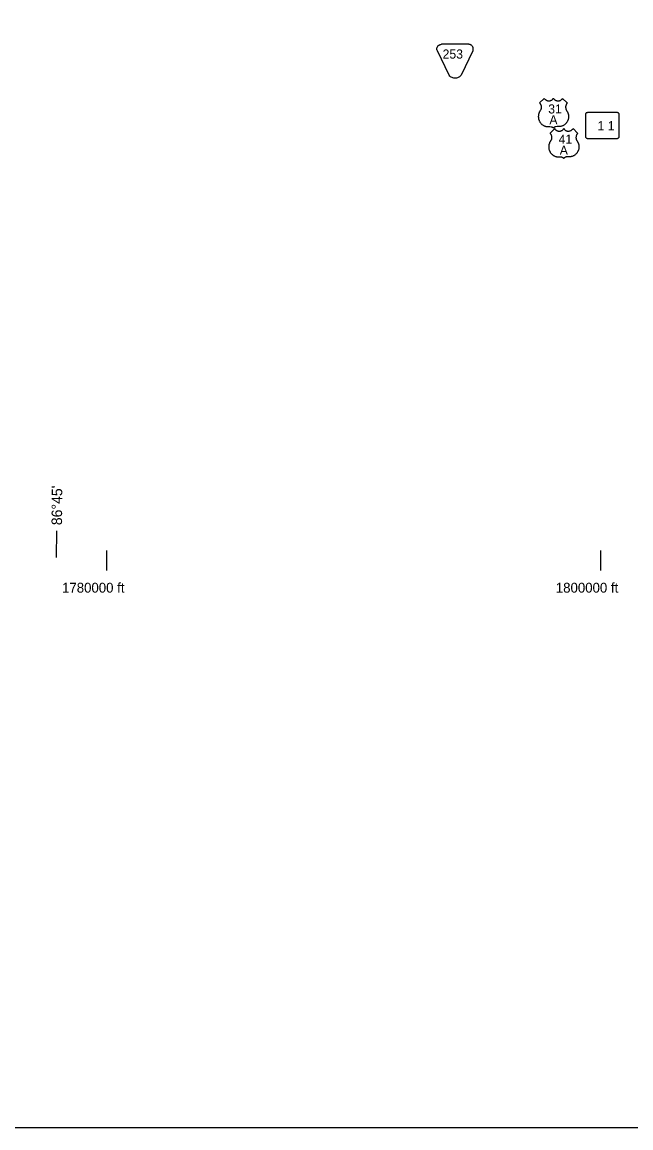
# Model space of a CAD drawing. Extents: x 1612280 to 1883141, y 560852 to 780851.
# Drawn here: x 1745083 to 1769718, y 560852 to 605620 of the extents above; entities that cross this region are included whole.
import ezdxf

# ---------------------------------------------------------------- set-up
doc = ezdxf.new("R2010")
doc.units = 0
for name, color, linetype in [('DESIGN - ROW - Easement Linework and Patterning', 7, 'Continuous'), ('DESIGN - ROW - Slope Lines', 7, 'Continuous'), ('DESIGN - SCRATCH - User 1', 7, 'Continuous'), ('SURVEY - DRAINAGE - Bridge Deck with Text', 7, 'Continuous'), ('SURVEY - DRAINAGE - Bridge Hydraulic Data - Points - Locators', 7, 'Continuous'), ('SURVEY - NON-TRANSPORTATION - Features - Points - Locators', 7, 'Continuous')]:
    doc.layers.add(name, color=color, linetype=linetype)

msp = doc.modelspace()

# ---------------------------------------------------------------- linework, layer by layer
at = {"layer": 'DESIGN - ROW - Easement Linework and Patterning'}
for points in [[(1762361, 603475), (1761886, 604456), (1761876, 604482), (1761871, 604501), (1761869, 604518), (1761868, 604534), (1761869, 604552), (1761871, 604568), (1761876, 604592), (1761883, 604609), (1761891, 604625), (1761901, 604641), (1761911, 604655), (1761927, 604671), (1761941, 604683), (1761954, 604692), (1761967, 604700), (1761983, 604707), (1761999, 604713), (1762012, 604716), (1762033, 604720), (1762053, 604721)], [(1762361, 603475), (1761886, 604456), (1761876, 604482), (1761871, 604501), (1761869, 604518), (1761868, 604534), (1761869, 604552), (1761871, 604568), (1761876, 604592), (1761883, 604609), (1761891, 604625), (1761901, 604641), (1761911, 604655), (1761927, 604671), (1761941, 604683), (1761954, 604692), (1761967, 604700), (1761983, 604707), (1761999, 604713), (1762012, 604716), (1762033, 604720), (1762053, 604721)], [(1763323, 604456), (1763330, 604473), (1763338, 604496), (1763340, 604513), (1763342, 604533), (1763341, 604549), (1763339, 604567), (1763334, 604589), (1763328, 604607), (1763321, 604622), (1763312, 604637), (1763300, 604653), (1763288, 604667), (1763269, 604683), (1763254, 604693), (1763240, 604701), (1763226, 604707), (1763210, 604713), (1763190, 604718), (1763176, 604720), (1763157, 604721), (1762053, 604721)], [(1763323, 604456), (1763330, 604473), (1763338, 604496), (1763340, 604513), (1763342, 604533), (1763341, 604549), (1763339, 604567), (1763334, 604589), (1763328, 604607), (1763321, 604622), (1763312, 604637), (1763300, 604653), (1763288, 604667), (1763269, 604683), (1763254, 604693), (1763240, 604701), (1763226, 604707), (1763210, 604713), (1763190, 604718), (1763176, 604720), (1763157, 604721), (1762053, 604721)], [(1763323, 604456), (1762850, 603478), (1762835, 603458), (1762821, 603441), (1762807, 603428), (1762779, 603405), (1762757, 603391), (1762733, 603378), (1762700, 603364), (1762663, 603354), (1762631, 603350), (1762596, 603349), (1762559, 603352), (1762518, 603361), (1762482, 603375), (1762447, 603394), (1762425, 603409), (1762395, 603434), (1762361, 603475)], [(1763323, 604456), (1762850, 603478), (1762835, 603458), (1762821, 603441), (1762807, 603428), (1762779, 603405), (1762757, 603391), (1762733, 603378), (1762700, 603364), (1762663, 603354), (1762631, 603350), (1762596, 603349), (1762559, 603352), (1762518, 603361), (1762482, 603375), (1762447, 603394), (1762425, 603409), (1762395, 603434), (1762361, 603475)]]:
    msp.add_lwpolyline(points, dxfattribs=at)
at = {"layer": 'DESIGN - ROW - Slope Lines'}
msp.add_line((1767876, 601855), (1767876, 601023), dxfattribs=at)
msp.add_line((1767876, 601855), (1767876, 601023), dxfattribs=at)
for points in [[(1769249, 601844), (1769249, 601852), (1769248, 601860), (1769247, 601875), (1769246, 601885), (1769244, 601896), (1769242, 601902), (1769239, 601908), (1769235, 601916), (1769229, 601923), (1769225, 601929), (1769219, 601934), (1769214, 601938), (1769208, 601943), (1769203, 601946), (1769194, 601950), (1769188, 601952), (1769181, 601953), (1769172, 601955), (1769164, 601955), (1769155, 601956), (1769143, 601956), (1769133, 601955), (1767976, 601956), (1767966, 601956), (1767956, 601955), (1767947, 601954), (1767938, 601953), (1767934, 601951), (1767926, 601948), (1767920, 601945), (1767915, 601942), (1767906, 601935), (1767900, 601929), (1767895, 601923), (1767891, 601918), (1767885, 601908), (1767882, 601901), (1767880, 601896), (1767879, 601892), (1767878, 601889), (1767878, 601881), (1767876, 601872), (1767876, 601864), (1767876, 601857), (1767876, 601839)], [(1769249, 601844), (1769249, 601852), (1769248, 601860), (1769247, 601875), (1769246, 601885), (1769244, 601896), (1769242, 601902), (1769239, 601908), (1769235, 601916), (1769229, 601923), (1769225, 601929), (1769219, 601934), (1769214, 601938), (1769208, 601943), (1769203, 601946), (1769194, 601950), (1769188, 601952), (1769181, 601953), (1769172, 601955), (1769164, 601955), (1769155, 601956), (1769143, 601956), (1769133, 601955), (1767976, 601956), (1767966, 601956), (1767956, 601955), (1767947, 601954), (1767938, 601953), (1767934, 601951), (1767926, 601948), (1767920, 601945), (1767915, 601942), (1767906, 601935), (1767900, 601929), (1767895, 601923), (1767891, 601918), (1767885, 601908), (1767882, 601901), (1767880, 601896), (1767879, 601892), (1767878, 601889), (1767878, 601881), (1767876, 601872), (1767876, 601864), (1767876, 601857), (1767876, 601839)], [(1769139, 600914), (1769160, 600914), (1769177, 600914), (1769187, 600917), (1769199, 600921), (1769210, 600928), (1769219, 600935), (1769227, 600943), (1769233, 600951), (1769239, 600960), (1769243, 600968), (1769246, 600975), (1769247, 600983), (1769248, 600991), (1769248, 601001), (1769249, 601024), (1769249, 601844)], [(1769139, 600914), (1769160, 600914), (1769177, 600914), (1769187, 600917), (1769199, 600921), (1769210, 600928), (1769219, 600935), (1769227, 600943), (1769233, 600951), (1769239, 600960), (1769243, 600968), (1769246, 600975), (1769247, 600983), (1769248, 600991), (1769248, 601001), (1769249, 601024), (1769249, 601844)], [(1767876, 601023), (1767876, 601014), (1767877, 601004), (1767877, 600994), (1767878, 600985), (1767880, 600976), (1767883, 600968), (1767886, 600961), (1767891, 600954), (1767896, 600946), (1767902, 600940), (1767909, 600933), (1767916, 600928), (1767924, 600923), (1767932, 600919), (1767941, 600916), (1767949, 600915), (1767963, 600914), (1767982, 600914), (1769139, 600914)], [(1767876, 601023), (1767876, 601014), (1767877, 601004), (1767877, 600994), (1767878, 600985), (1767880, 600976), (1767883, 600968), (1767886, 600961), (1767891, 600954), (1767896, 600946), (1767902, 600940), (1767909, 600933), (1767916, 600928), (1767924, 600923), (1767932, 600919), (1767941, 600916), (1767949, 600915), (1767963, 600914), (1767982, 600914), (1769139, 600914)]]:
    msp.add_lwpolyline(points, dxfattribs=at)
at = {"layer": 'DESIGN - SCRATCH - User 1'}
msp.add_lwpolyline([(1612280, 780851), (1883141, 780851), (1883141, 560852), (1612280, 560852)], close=True, dxfattribs=at)
msp.add_lwpolyline([(1612280, 780851), (1883141, 780851), (1883141, 560852), (1612280, 560852)], close=True, dxfattribs=at)
at = {"layer": 'SURVEY - DRAINAGE - Bridge Deck with Text'}
for points in [[(1766026, 602346), (1766035, 602336), (1766043, 602325), (1766051, 602314), (1766057, 602304), (1766064, 602291), (1766071, 602277), (1766076, 602263), (1766081, 602248), (1766085, 602233), (1766088, 602217), (1766091, 602200), (1766092, 602178), (1766092, 602162), (1766090, 602146), (1766088, 602132), (1766084, 602113), (1766080, 602100), (1766076, 602086), (1766071, 602074), (1766066, 602064), (1766058, 602050), (1766051, 602038), (1766040, 602020), (1766028, 601999), (1766024, 601993), (1766018, 601982), (1766011, 601969), (1766007, 601960), (1766002, 601948), (1765998, 601938), (1765994, 601927), (1765991, 601915), (1765987, 601903), (1765983, 601889), (1765981, 601878), (1765979, 601866), (1765977, 601854), (1765975, 601841), (1765974, 601830), (1765973, 601818), (1765972, 601807), (1765972, 601796), (1765972, 601784), (1765973, 601772), (1765974, 601758), (1765976, 601743), (1765978, 601727), (1765981, 601713), (1765984, 601696), (1765989, 601677), (1765994, 601663), (1766001, 601645), (1766007, 601631), (1766012, 601620), (1766019, 601605), (1766029, 601588), (1766038, 601573), (1766050, 601555), (1766062, 601539), (1766076, 601523), (1766091, 601507), (1766103, 601496), (1766120, 601481), (1766140, 601465), (1766164, 601449), (1766184, 601437), (1766204, 601427), (1766222, 601419), (1766242, 601411), (1766262, 601405), (1766281, 601400), (1766291, 601397), (1766304, 601396), (1766334, 601393), (1766439, 601390), (1766487, 601387), (1766492, 601387), (1766496, 601386), (1766502, 601384), (1766507, 601383), (1766511, 601381), (1766516, 601380), (1766521, 601377), (1766526, 601375), (1766531, 601373), (1766535, 601371), (1766539, 601369), (1766547, 601363), (1766556, 601356), (1766565, 601349), (1766572, 601342), (1766579, 601334), (1766584, 601326)], [(1766026, 602346), (1766035, 602336), (1766043, 602325), (1766051, 602314), (1766057, 602304), (1766064, 602291), (1766071, 602277), (1766076, 602263), (1766081, 602248), (1766085, 602233), (1766088, 602217), (1766091, 602200), (1766092, 602178), (1766092, 602162), (1766090, 602146), (1766088, 602132), (1766084, 602113), (1766080, 602100), (1766076, 602086), (1766071, 602074), (1766066, 602064), (1766058, 602050), (1766051, 602038), (1766040, 602020), (1766028, 601999), (1766024, 601993), (1766018, 601982), (1766011, 601969), (1766007, 601960), (1766002, 601948), (1765998, 601938), (1765994, 601927), (1765991, 601915), (1765987, 601903), (1765983, 601889), (1765981, 601878), (1765979, 601866), (1765977, 601854), (1765975, 601841), (1765974, 601830), (1765973, 601818), (1765972, 601807), (1765972, 601796), (1765972, 601784), (1765973, 601772), (1765974, 601758), (1765976, 601743), (1765978, 601727), (1765981, 601713), (1765984, 601696), (1765989, 601677), (1765994, 601663), (1766001, 601645), (1766007, 601631), (1766012, 601620), (1766019, 601605), (1766029, 601588), (1766038, 601573), (1766050, 601555), (1766062, 601539), (1766076, 601523), (1766091, 601507), (1766103, 601496), (1766120, 601481), (1766140, 601465), (1766164, 601449), (1766184, 601437), (1766204, 601427), (1766222, 601419), (1766242, 601411), (1766262, 601405), (1766281, 601400), (1766291, 601397), (1766304, 601396), (1766334, 601393), (1766439, 601390), (1766487, 601387), (1766492, 601387), (1766496, 601386), (1766502, 601384), (1766507, 601383), (1766511, 601381), (1766516, 601380), (1766521, 601377), (1766526, 601375), (1766531, 601373), (1766535, 601371), (1766539, 601369), (1766547, 601363), (1766556, 601356), (1766565, 601349), (1766572, 601342), (1766579, 601334), (1766584, 601326)], [(1766026, 602346), (1766214, 602533), (1766223, 602519), (1766236, 602504), (1766248, 602492), (1766259, 602482), (1766271, 602473), (1766284, 602464), (1766297, 602457), (1766311, 602451), (1766324, 602445), (1766341, 602440), (1766356, 602436), (1766373, 602434), (1766390, 602432), (1766398, 602432), (1766406, 602432), (1766414, 602433), (1766424, 602434), (1766435, 602435), (1766448, 602438), (1766461, 602441), (1766479, 602447), (1766496, 602455), (1766513, 602464), (1766527, 602473), (1766540, 602483), (1766554, 602495), (1766566, 602508), (1766577, 602522), (1766585, 602533), (1766592, 602523), (1766600, 602512), (1766608, 602503), (1766618, 602493), (1766629, 602483), (1766642, 602473), (1766655, 602465), (1766669, 602457), (1766684, 602450), (1766703, 602443), (1766724, 602437), (1766745, 602434), (1766763, 602432), (1766783, 602433), (1766803, 602435), (1766824, 602439), (1766846, 602446), (1766864, 602453), (1766878, 602460), (1766895, 602471), (1766909, 602481), (1766925, 602495), (1766936, 602507), (1766946, 602519), (1766956, 602533), (1767143, 602346)], [(1766026, 602346), (1766214, 602533), (1766223, 602519), (1766236, 602504), (1766248, 602492), (1766259, 602482), (1766271, 602473), (1766284, 602464), (1766297, 602457), (1766311, 602451), (1766324, 602445), (1766341, 602440), (1766356, 602436), (1766373, 602434), (1766390, 602432), (1766398, 602432), (1766406, 602432), (1766414, 602433), (1766424, 602434), (1766435, 602435), (1766448, 602438), (1766461, 602441), (1766479, 602447), (1766496, 602455), (1766513, 602464), (1766527, 602473), (1766540, 602483), (1766554, 602495), (1766566, 602508), (1766577, 602522), (1766585, 602533), (1766592, 602523), (1766600, 602512), (1766608, 602503), (1766618, 602493), (1766629, 602483), (1766642, 602473), (1766655, 602465), (1766669, 602457), (1766684, 602450), (1766703, 602443), (1766724, 602437), (1766745, 602434), (1766763, 602432), (1766783, 602433), (1766803, 602435), (1766824, 602439), (1766846, 602446), (1766864, 602453), (1766878, 602460), (1766895, 602471), (1766909, 602481), (1766925, 602495), (1766936, 602507), (1766946, 602519), (1766956, 602533), (1767143, 602346)], [(1767143, 602346), (1767134, 602336), (1767125, 602325), (1767118, 602314), (1767111, 602304), (1767105, 602291), (1767098, 602277), (1767093, 602263), (1767087, 602248), (1767084, 602233), (1767080, 602217), (1767078, 602200), (1767077, 602178), (1767077, 602162), (1767079, 602146), (1767081, 602132), (1767085, 602113), (1767089, 602100), (1767093, 602086), (1767098, 602074), (1767103, 602064), (1767111, 602050), (1767118, 602038), (1767128, 602020), (1767141, 601999), (1767145, 601993), (1767151, 601982), (1767157, 601969), (1767162, 601960), (1767166, 601948), (1767171, 601938), (1767174, 601927), (1767178, 601915), (1767182, 601903), (1767185, 601889), (1767188, 601878), (1767190, 601866), (1767192, 601854), (1767194, 601841), (1767195, 601830), (1767196, 601818), (1767196, 601807), (1767197, 601796), (1767197, 601784), (1767196, 601772), (1767195, 601758), (1767193, 601743), (1767191, 601727), (1767188, 601713), (1767185, 601696), (1767179, 601677), (1767175, 601663), (1767168, 601645), (1767162, 601631), (1767157, 601620), (1767150, 601605), (1767140, 601588), (1767131, 601573), (1767119, 601555), (1767107, 601539), (1767093, 601523), (1767078, 601507), (1767066, 601496), (1767049, 601481), (1767029, 601465), (1767005, 601449), (1766985, 601437), (1766965, 601427), (1766947, 601419), (1766926, 601411), (1766907, 601405), (1766888, 601400), (1766878, 601397), (1766865, 601396), (1766835, 601393), (1766730, 601390), (1766682, 601387), (1766677, 601387), (1766673, 601386), (1766667, 601384), (1766662, 601383), (1766658, 601381), (1766653, 601380), (1766648, 601377), (1766643, 601375), (1766638, 601373), (1766634, 601371), (1766630, 601369), (1766622, 601363), (1766613, 601356), (1766604, 601349), (1766596, 601342), (1766590, 601334), (1766584, 601326)], [(1767143, 602346), (1767134, 602336), (1767125, 602325), (1767118, 602314), (1767111, 602304), (1767105, 602291), (1767098, 602277), (1767093, 602263), (1767087, 602248), (1767084, 602233), (1767080, 602217), (1767078, 602200), (1767077, 602178), (1767077, 602162), (1767079, 602146), (1767081, 602132), (1767085, 602113), (1767089, 602100), (1767093, 602086), (1767098, 602074), (1767103, 602064), (1767111, 602050), (1767118, 602038), (1767128, 602020), (1767141, 601999), (1767145, 601993), (1767151, 601982), (1767157, 601969), (1767162, 601960), (1767166, 601948), (1767171, 601938), (1767174, 601927), (1767178, 601915), (1767182, 601903), (1767185, 601889), (1767188, 601878), (1767190, 601866), (1767192, 601854), (1767194, 601841), (1767195, 601830), (1767196, 601818), (1767196, 601807), (1767197, 601796), (1767197, 601784), (1767196, 601772), (1767195, 601758), (1767193, 601743), (1767191, 601727), (1767188, 601713), (1767185, 601696), (1767179, 601677), (1767175, 601663), (1767168, 601645), (1767162, 601631), (1767157, 601620), (1767150, 601605), (1767140, 601588), (1767131, 601573), (1767119, 601555), (1767107, 601539), (1767093, 601523), (1767078, 601507), (1767066, 601496), (1767049, 601481), (1767029, 601465), (1767005, 601449), (1766985, 601437), (1766965, 601427), (1766947, 601419), (1766926, 601411), (1766907, 601405), (1766888, 601400), (1766878, 601397), (1766865, 601396), (1766835, 601393), (1766730, 601390), (1766682, 601387), (1766677, 601387), (1766673, 601386), (1766667, 601384), (1766662, 601383), (1766658, 601381), (1766653, 601380), (1766648, 601377), (1766643, 601375), (1766638, 601373), (1766634, 601371), (1766630, 601369), (1766622, 601363), (1766613, 601356), (1766604, 601349), (1766596, 601342), (1766590, 601334), (1766584, 601326)], [(1766446, 601121), (1766634, 601307), (1766643, 601293), (1766656, 601278), (1766668, 601266), (1766679, 601256), (1766691, 601247), (1766704, 601239), (1766717, 601232), (1766731, 601225), (1766744, 601220), (1766761, 601214), (1766776, 601211), (1766793, 601208), (1766810, 601207), (1766818, 601206), (1766826, 601207), (1766834, 601207), (1766844, 601208), (1766855, 601209), (1766868, 601212), (1766881, 601215), (1766899, 601221), (1766916, 601229), (1766933, 601238), (1766947, 601247), (1766960, 601257), (1766974, 601269), (1766986, 601282), (1766997, 601296), (1767005, 601307), (1767012, 601297), (1767020, 601286), (1767028, 601277), (1767038, 601267), (1767049, 601257), (1767062, 601248), (1767075, 601239), (1767089, 601231), (1767104, 601224), (1767123, 601217), (1767144, 601211), (1767165, 601208), (1767183, 601207), (1767203, 601207), (1767223, 601209), (1767244, 601213), (1767266, 601220), (1767284, 601227), (1767298, 601234), (1767315, 601245), (1767329, 601256), (1767345, 601270), (1767356, 601281), (1767366, 601293), (1767376, 601307), (1767563, 601121)], [(1766446, 601121), (1766634, 601307), (1766643, 601293), (1766656, 601278), (1766668, 601266), (1766679, 601256), (1766691, 601247), (1766704, 601239), (1766717, 601232), (1766731, 601225), (1766744, 601220), (1766761, 601214), (1766776, 601211), (1766793, 601208), (1766810, 601207), (1766818, 601206), (1766826, 601207), (1766834, 601207), (1766844, 601208), (1766855, 601209), (1766868, 601212), (1766881, 601215), (1766899, 601221), (1766916, 601229), (1766933, 601238), (1766947, 601247), (1766960, 601257), (1766974, 601269), (1766986, 601282), (1766997, 601296), (1767005, 601307), (1767012, 601297), (1767020, 601286), (1767028, 601277), (1767038, 601267), (1767049, 601257), (1767062, 601248), (1767075, 601239), (1767089, 601231), (1767104, 601224), (1767123, 601217), (1767144, 601211), (1767165, 601208), (1767183, 601207), (1767203, 601207), (1767223, 601209), (1767244, 601213), (1767266, 601220), (1767284, 601227), (1767298, 601234), (1767315, 601245), (1767329, 601256), (1767345, 601270), (1767356, 601281), (1767366, 601293), (1767376, 601307), (1767563, 601121)], [(1766446, 601121), (1766455, 601110), (1766463, 601099), (1766471, 601088), (1766477, 601078), (1766484, 601065), (1766491, 601051), (1766496, 601037), (1766501, 601022), (1766505, 601008), (1766508, 600992), (1766511, 600974), (1766512, 600952), (1766511, 600936), (1766510, 600920), (1766508, 600906), (1766504, 600888), (1766500, 600874), (1766496, 600861), (1766491, 600849), (1766486, 600838), (1766478, 600824), (1766471, 600812), (1766460, 600794), (1766448, 600773), (1766444, 600767), (1766438, 600756), (1766431, 600743), (1766427, 600734), (1766422, 600722), (1766418, 600712), (1766414, 600701), (1766411, 600689), (1766407, 600677), (1766403, 600663), (1766401, 600652), (1766399, 600640), (1766397, 600628), (1766395, 600616), (1766394, 600604), (1766393, 600592), (1766392, 600582), (1766392, 600570), (1766392, 600558), (1766393, 600546), (1766394, 600532), (1766396, 600517), (1766398, 600501), (1766401, 600487), (1766404, 600470), (1766409, 600451), (1766414, 600437), (1766421, 600419), (1766427, 600406), (1766432, 600394), (1766439, 600379), (1766449, 600362), (1766458, 600347), (1766470, 600330), (1766482, 600313), (1766496, 600297), (1766511, 600282), (1766523, 600270), (1766540, 600255), (1766560, 600240), (1766584, 600223), (1766604, 600212), (1766624, 600202), (1766642, 600193), (1766662, 600185), (1766682, 600179), (1766701, 600174), (1766711, 600171), (1766724, 600170), (1766754, 600167), (1766859, 600164), (1766907, 600161), (1766912, 600161), (1766916, 600160), (1766921, 600158), (1766927, 600157), (1766931, 600155), (1766936, 600154), (1766941, 600152), (1766946, 600150), (1766951, 600147), (1766955, 600145), (1766959, 600143), (1766967, 600137), (1766976, 600131), (1766985, 600123), (1766992, 600116), (1766999, 600108), (1767004, 600100)], [(1766446, 601121), (1766455, 601110), (1766463, 601099), (1766471, 601088), (1766477, 601078), (1766484, 601065), (1766491, 601051), (1766496, 601037), (1766501, 601022), (1766505, 601008), (1766508, 600992), (1766511, 600974), (1766512, 600952), (1766511, 600936), (1766510, 600920), (1766508, 600906), (1766504, 600888), (1766500, 600874), (1766496, 600861), (1766491, 600849), (1766486, 600838), (1766478, 600824), (1766471, 600812), (1766460, 600794), (1766448, 600773), (1766444, 600767), (1766438, 600756), (1766431, 600743), (1766427, 600734), (1766422, 600722), (1766418, 600712), (1766414, 600701), (1766411, 600689), (1766407, 600677), (1766403, 600663), (1766401, 600652), (1766399, 600640), (1766397, 600628), (1766395, 600616), (1766394, 600604), (1766393, 600592), (1766392, 600582), (1766392, 600570), (1766392, 600558), (1766393, 600546), (1766394, 600532), (1766396, 600517), (1766398, 600501), (1766401, 600487), (1766404, 600470), (1766409, 600451), (1766414, 600437), (1766421, 600419), (1766427, 600406), (1766432, 600394), (1766439, 600379), (1766449, 600362), (1766458, 600347), (1766470, 600330), (1766482, 600313), (1766496, 600297), (1766511, 600282), (1766523, 600270), (1766540, 600255), (1766560, 600240), (1766584, 600223), (1766604, 600212), (1766624, 600202), (1766642, 600193), (1766662, 600185), (1766682, 600179), (1766701, 600174), (1766711, 600171), (1766724, 600170), (1766754, 600167), (1766859, 600164), (1766907, 600161), (1766912, 600161), (1766916, 600160), (1766921, 600158), (1766927, 600157), (1766931, 600155), (1766936, 600154), (1766941, 600152), (1766946, 600150), (1766951, 600147), (1766955, 600145), (1766959, 600143), (1766967, 600137), (1766976, 600131), (1766985, 600123), (1766992, 600116), (1766999, 600108), (1767004, 600100)], [(1767563, 601121), (1767554, 601110), (1767545, 601099), (1767538, 601088), (1767531, 601078), (1767525, 601065), (1767518, 601051), (1767512, 601037), (1767507, 601022), (1767504, 601008), (1767500, 600992), (1767498, 600974), (1767497, 600952), (1767497, 600936), (1767499, 600920), (1767501, 600906), (1767505, 600888), (1767509, 600874), (1767513, 600861), (1767518, 600849), (1767523, 600838), (1767531, 600824), (1767538, 600812), (1767548, 600794), (1767561, 600773), (1767565, 600767), (1767571, 600756), (1767577, 600743), (1767582, 600734), (1767586, 600723), (1767591, 600712), (1767594, 600701), (1767598, 600689), (1767602, 600677), (1767605, 600663), (1767608, 600652), (1767610, 600640), (1767612, 600628), (1767614, 600616), (1767615, 600604), (1767616, 600592), (1767616, 600582), (1767617, 600570), (1767617, 600558), (1767616, 600546), (1767615, 600532), (1767613, 600517), (1767611, 600502), (1767608, 600487), (1767605, 600470), (1767599, 600451), (1767595, 600437), (1767588, 600419), (1767582, 600406), (1767577, 600394), (1767570, 600379), (1767560, 600362), (1767551, 600347), (1767539, 600330), (1767527, 600313), (1767513, 600297), (1767498, 600282), (1767486, 600270), (1767469, 600255), (1767449, 600240), (1767425, 600223), (1767405, 600212), (1767385, 600202), (1767367, 600193), (1767346, 600185), (1767327, 600179), (1767308, 600174), (1767298, 600171), (1767285, 600170), (1767255, 600167), (1767150, 600164), (1767102, 600161), (1767097, 600161), (1767093, 600160), (1767087, 600158), (1767082, 600157), (1767078, 600155), (1767073, 600154), (1767068, 600152), (1767063, 600150), (1767058, 600147), (1767054, 600145), (1767050, 600143), (1767042, 600137), (1767033, 600131), (1767024, 600123), (1767016, 600116), (1767010, 600108), (1767004, 600100)], [(1767563, 601121), (1767554, 601110), (1767545, 601099), (1767538, 601088), (1767531, 601078), (1767525, 601065), (1767518, 601051), (1767512, 601037), (1767507, 601022), (1767504, 601008), (1767500, 600992), (1767498, 600974), (1767497, 600952), (1767497, 600936), (1767499, 600920), (1767501, 600906), (1767505, 600888), (1767509, 600874), (1767513, 600861), (1767518, 600849), (1767523, 600838), (1767531, 600824), (1767538, 600812), (1767548, 600794), (1767561, 600773), (1767565, 600767), (1767571, 600756), (1767577, 600743), (1767582, 600734), (1767586, 600723), (1767591, 600712), (1767594, 600701), (1767598, 600689), (1767602, 600677), (1767605, 600663), (1767608, 600652), (1767610, 600640), (1767612, 600628), (1767614, 600616), (1767615, 600604), (1767616, 600592), (1767616, 600582), (1767617, 600570), (1767617, 600558), (1767616, 600546), (1767615, 600532), (1767613, 600517), (1767611, 600502), (1767608, 600487), (1767605, 600470), (1767599, 600451), (1767595, 600437), (1767588, 600419), (1767582, 600406), (1767577, 600394), (1767570, 600379), (1767560, 600362), (1767551, 600347), (1767539, 600330), (1767527, 600313), (1767513, 600297), (1767498, 600282), (1767486, 600270), (1767469, 600255), (1767449, 600240), (1767425, 600223), (1767405, 600212), (1767385, 600202), (1767367, 600193), (1767346, 600185), (1767327, 600179), (1767308, 600174), (1767298, 600171), (1767285, 600170), (1767255, 600167), (1767150, 600164), (1767102, 600161), (1767097, 600161), (1767093, 600160), (1767087, 600158), (1767082, 600157), (1767078, 600155), (1767073, 600154), (1767068, 600152), (1767063, 600150), (1767058, 600147), (1767054, 600145), (1767050, 600143), (1767042, 600137), (1767033, 600131), (1767024, 600123), (1767016, 600116), (1767010, 600108), (1767004, 600100)]]:
    msp.add_lwpolyline(points, dxfattribs=at)
at = {"layer": 'SURVEY - DRAINAGE - Bridge Hydraulic Data - Points - Locators'}
msp.add_line((1746476, 583950), (1746485, 585022), dxfattribs=at)
msp.add_line((1746476, 583950), (1746485, 585022), dxfattribs=at)
at = {"layer": 'SURVEY - NON-TRANSPORTATION - Features - Points - Locators'}
for p, q in [((1748505, 583422), (1748505, 584222)), ((1748505, 583422), (1748505, 584222)), ((1768505, 583422), (1768505, 584222)), ((1768505, 583422), (1768505, 584222))]:
    msp.add_line(p, q, dxfattribs=at)

# ---------------------------------------------------------------- texts
at = {"layer": 'DESIGN - ROW - Easement Linework and Patterning'}
msp.add_text('253', height=369.6, rotation=0.0012, dxfattribs=at).set_placement((1762099, 604143))
msp.add_text('253', height=369.6, rotation=0.0012, dxfattribs=at).set_placement((1762099, 604143))
at = {"layer": 'DESIGN - ROW - Slope Lines'}
msp.add_text('1 1', height=369.6, rotation=0.0011, dxfattribs=at).set_placement((1768368, 601241))
msp.add_text('1 1', height=369.6, rotation=0.0011, dxfattribs=at).set_placement((1768368, 601241))
at = {"layer": 'SURVEY - DRAINAGE - Bridge Deck with Text'}
for s, height, p in [('31', 369.6, (1766373, 601921)), ('31', 369.6, (1766373, 601921)), ('A', 370, (1766419, 601479)), ('A', 370, (1766419, 601479)), ('41', 369.6, (1766792, 600695)), ('41', 369.6, (1766792, 600695)), ('A', 370, (1766839, 600253)), ('A', 370, (1766839, 600253))]:
    msp.add_text(s, height=height, rotation=0.0014, dxfattribs=at).set_placement(p)
at = {"layer": 'SURVEY - DRAINAGE - Bridge Hydraulic Data - Points - Locators'}
msp.add_text("86°45'", height=425, rotation=89.5609, dxfattribs=at).set_placement((1746697, 585252))
msp.add_text("86°45'", height=425, rotation=89.5609, dxfattribs=at).set_placement((1746697, 585252))
at = {"layer": 'SURVEY - NON-TRANSPORTATION - Features - Points - Locators'}
for s, p in [('1780000 ft', (1746698, 582522)), ('1780000 ft', (1746698, 582522)), ('1800000 ft', (1766680, 582522)), ('1800000 ft', (1766680, 582522))]:
    msp.add_text(s, height=400, rotation=0, dxfattribs=at).set_placement(p)

doc.saveas('drawing.dxf')
